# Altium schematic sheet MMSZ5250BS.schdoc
size 127 x 101 mm
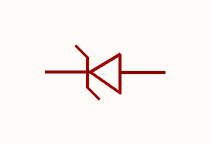
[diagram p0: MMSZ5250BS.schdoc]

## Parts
ZD?  mmsz5250bs  [SOD-323_L1.8-W1.3-LS2.5-RD]  (value not drawn)

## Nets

Not connected (* = marked no-connect by the designer): ZD? 1(K) 2(A)

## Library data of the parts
ZD? = mmsz5250bs: 二极管配置:1个独立式;稳压值(标称值):20V;稳压值(范围):19V~21V;耗散功率(Pd):200mW;; Manufacturer: CJ(江苏长电/长晶); AddInBom: yes; ModelId: db63db13d9e342eb939127d413d6200b; ModelTransform: 104.3305,51.181,0,0,0,0,0,-0.004,0; Diode Configuration: 1个独立式; Zener Voltage(Nom): 20V; Reverse Leakage Current (Ir): 100nA; Pd - Power Dissipation: 200mW; Impedance(Zzt): 25Ω; Impedance(Zzk): 600Ω; Operating Junction Temperature Range: -65℃~+150℃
